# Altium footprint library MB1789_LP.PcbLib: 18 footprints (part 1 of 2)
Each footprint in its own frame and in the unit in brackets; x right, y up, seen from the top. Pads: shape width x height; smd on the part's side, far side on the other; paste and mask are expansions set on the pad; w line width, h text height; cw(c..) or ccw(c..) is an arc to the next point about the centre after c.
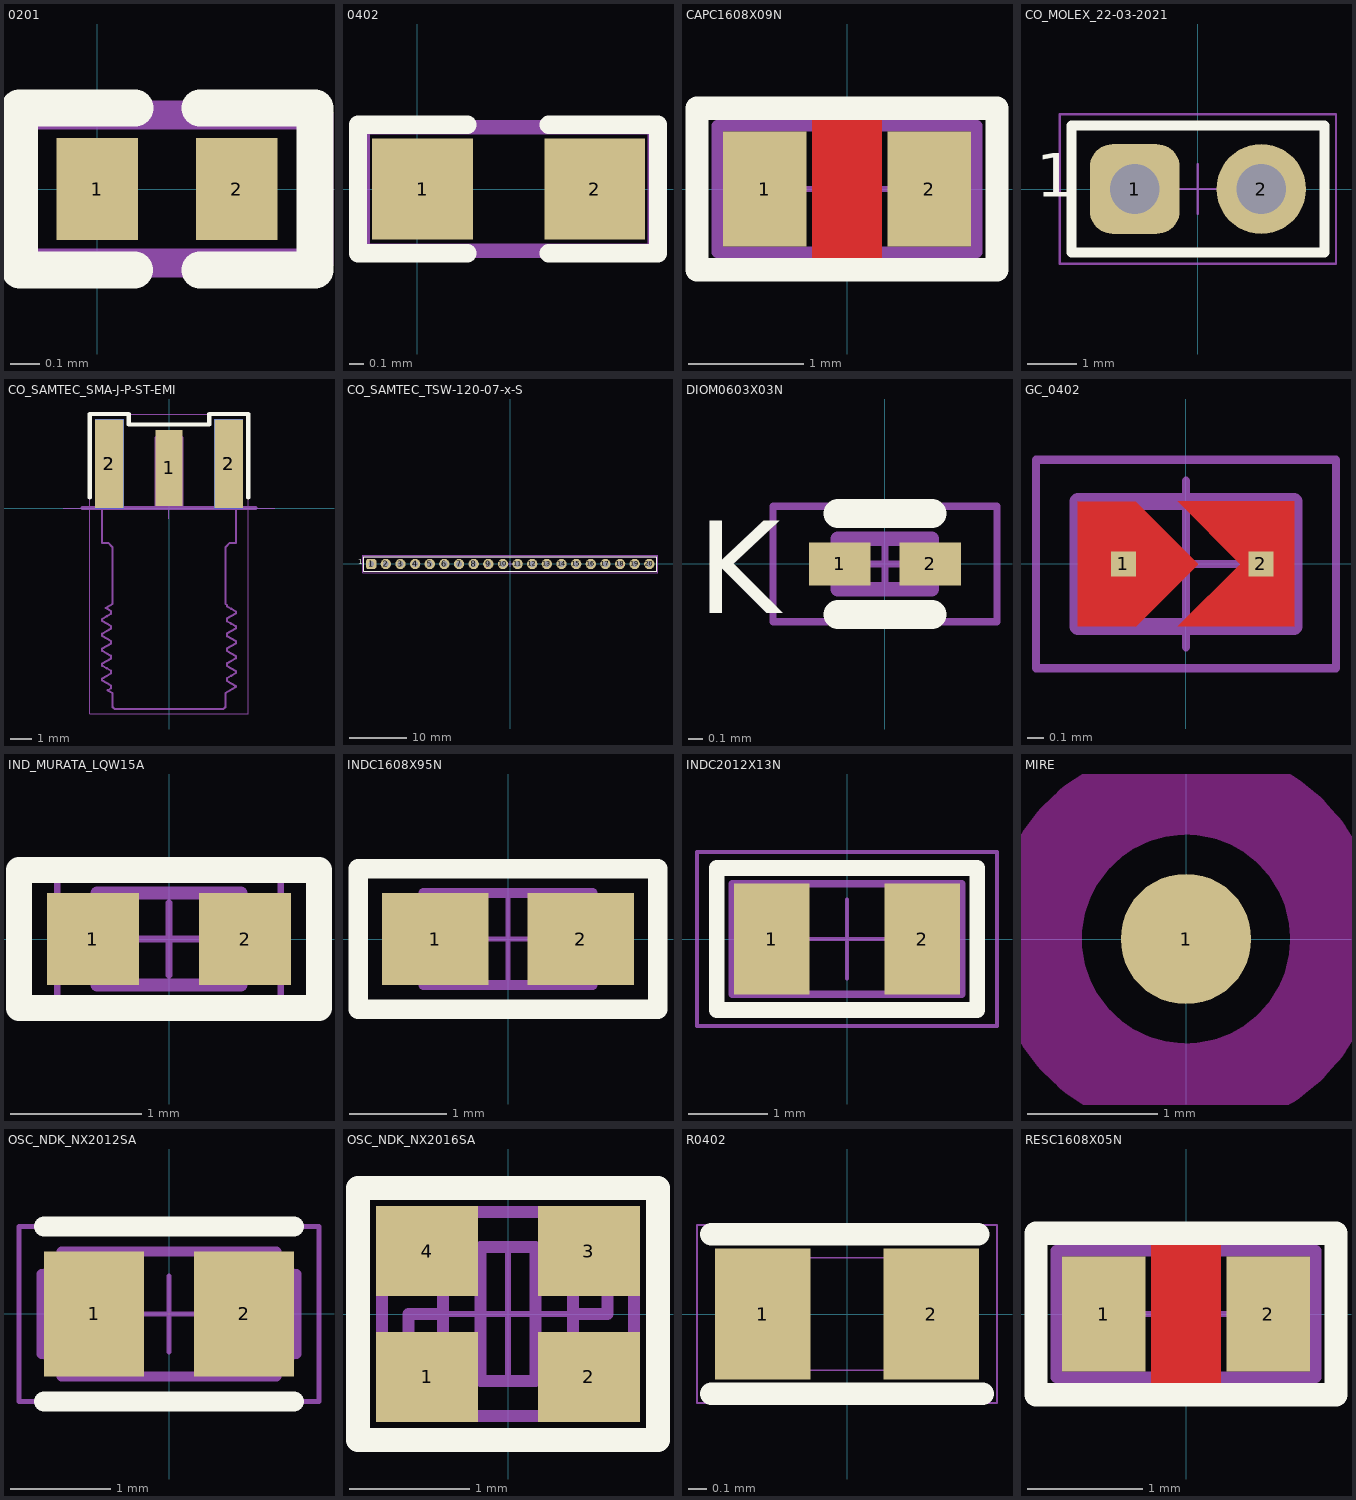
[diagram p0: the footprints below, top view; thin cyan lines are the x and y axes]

## 0201 [mm]
pads (2):
  rect 0.28x0.35 smd: 1(0,0) 2(0.48,0)
Top Overlay:
  lines w0.127: -0.268,0.279 0.13,0.279 ; -0.267,0.273 -0.267,-0.278 0.128,-0.278 ; 0.353,0.279 0.748,0.279 0.748,-0.278 0.354,-0.278
Top Assembly (Mech14):
  lines w0.1: -0.254,-0.254 0.762,-0.254 0.762,0.254 -0.254,0.254 -0.254,-0.254
  text ".Designator" at -0.44,-0.035 h1.25
3D body "User Library-Chip Cap_MLCC_0201 (0603).step": height 0.3, standoff 0, extent -0.062,-0.149 0.538,0.151

## 0402 [mm]
pads (2):
  rect 0.7x0.7 smd: 1(0.035,0) 2(1.233,0)
Top Overlay:
  lines w0.127: -0.414,-0.447 -0.414,0.447 ; -0.384,-0.447 0.348,-0.447 ; -0.384,0.447 0.348,0.447 ; 0.913,-0.447 1.674,-0.447 ; 0.913,0.447 1.674,0.447 ; 1.674,-0.444 1.674,0.444
Top Assembly (Mech14):
  lines w0.1: -0.381,-0.43 -0.381,0.431 1.651,0.431 1.651,-0.43 -0.381,-0.43
  text ".Designator" at -0.508,0.381 h1.25
3D body: height 0.82, standoff 0, extent -0.38,-0.356 0.027,0.356
3D body: height 0.82, standoff 0, extent 1.246,-0.356 1.652,0.356
3D body: height 0.77, standoff 0, extent 0.027,-0.305 1.246,0.33

## CAPC1608X09N [mm] "Chip Capacitor, 2-Leads, Body 1.60x0.80x0.90mm (0603)"
height 0.9
pads (2):
  rect 0.725x1 smd: 1(-0.713,0) 2(0.713,0)
Top Layer:
  pour cut-out: -0.3,0.7 0.3,0.7 0.3,-0.7 -0.3,-0.7
Top Overlay:
  lines w0.2: -1.3,-0.7 -1.3,0.7 1.3,0.7 1.3,-0.7 -1.3,-0.7
Top Assembly (Mech14):
  lines w0.1: -1.125,-0.55 1.125,-0.55 1.125,0.55 -1.125,0.55 -1.125,-0.55
  text ".Designator" at 0.65,0.4 h1.25
Mechanical 17:
  lines w0.05: -0.5,0 0.5,0 ; 0,-0.5 0,0.5 ; -1.3,-0.7 1.3,-0.7 1.3,0.7 -1.3,0.7 -1.3,-0.7
3D body "CAPC1608X09.step": height 0.9, standoff 0, extent -0.8,-0.4 0.8,0.4

## CO_MOLEX_22-03-2021 [mm]
height 10.8
pads (2):
  rrect50% 1.8x1.8 hole 1: 1(-1.27,0)
  round 1.8 hole 1: 2(1.27,0)
Top Overlay:
  lines w0.2: -2.54,-1.27 -2.54,1.27 2.54,1.27 2.54,-1.27 -2.54,-1.27
  text "1" at -3.25,-0.45 h1.5
Top Assembly (Mech14):
  lines w0.1: -2.54,-1.27 -2.54,1.27 2.54,1.27 2.54,-1.27 -2.54,-1.27
  text ".Designator" at 0.4,-0.55 h1.25
  text "1" at -1.6,-1.85 h1.25
Mechanical 17:
  lines w0.05: -0.5,0 0.5,0 ; 0,-0.5 0,0.5 ; -2.77,-1.5 2.77,-1.5 2.77,1.5 -2.77,1.5 -2.77,-1.5
3D body "022032021.stp": height 10.79, standoff -3.43, extent -2.413,-1.181 2.413,1.181

## CO_SAMTEC_SMA-J-P-ST-EMI [mm] "SMA Jack CMS, Edge Mountt Receptacle 50Ohm, 5-Leads, Body 6.35x6.35x9.52mm, pitch 2.825mm"
height 6.35
pads (5):
  rect 1.27x3.6 smd mask+0.05: 1(0,1.9)
  rect 1.35x4.2 smd mask+0.05: 2(-2.825,2.1) 2(2.825,2.1)
  rect 1.35x4.2 smd far side mask+0.05: 2(-2.825,2.1) 2(2.825,2.1)
Top Overlay:
  lines w0.2: -3.75,0.5 -3.75,4.45 -1.9,4.45 -1.9,3.95 1.9,3.95 1.9,4.45 3.75,4.45 3.75,0.5
Mechanical 10:
  lines w0.2: -4.1,0 4.1,0
  text "Edge of PCB" at -2,-0.825 h0.8
Top Assembly (Mech14):
  lines w0.1: -3.164,-8.074 -3.164,-8.162 -3.15,-8.169 ; -3.164,-7.369 -3.164,-7.456 -3.15,-7.464 ; -3.164,-6.663 -3.164,-6.751 -3.15,-6.758 ; -3.164,-5.958 -3.164,-6.045 -3.151,-6.052 ; -3.164,-5.252 -3.164,-5.34 -3.152,-5.346 ; -3.158,-6.052 -2.948,-6.173 -2.744,-6.291 ; -3.159,-5.951 -2.949,-5.829 -2.739,-5.708 ; -3.159,-5.346 -2.949,-5.468 -2.744,-5.586 ; -3.158,-5.245 -2.948,-5.124 -2.738,-5.002 ; -3.157,-8.169 -2.947,-8.291 -2.744,-8.408 ; -3.157,-8.067 -2.947,-7.945 -2.737,-7.823 ; -3.157,-7.464 -2.947,-7.585 -2.744,-7.703 ; -3.157,-7.361 -2.947,-7.24 -2.737,-7.118 ; -3.157,-6.758 -2.947,-6.88 -2.744,-6.997 ; -3.157,-6.656 -2.947,-6.534 -2.737,-6.413 ; -2.992,-4.737 -2.947,-4.763 -2.744,-4.88 ; -2.991,-4.732 -2.675,-4.55 -2.675,-1.85 -2.875,-1.65 -3.175,-1.65 -3.175,0 -3.175,3.81 -2.365,3.81 -2.365,0 -0.635,0 -0.635,3.335 -0.335,3.635 0,3.635 0.335,3.635 0.635,3.335 0.635,0 2.365,0 2.365,3.81 3.175,3.81 3.175,0 3.175,-1.65 2.875,-1.65 2.675,-1.85 2.675,-4.55 2.744,-4.59 2.744,-4.653 2.947,-4.77 3.157,-4.892 ; -2.9,-8.63 -2.675,-8.76 -2.675,-9.42 -2.575,-9.52 0,-9.52 2.575,-9.52 2.675,-9.42 2.675,-8.76 3.164,-8.478 3.164,-8.427 3.152,-8.42 ; -2.901,-8.624 -2.737,-8.529 ; -2.744,-8.533 -2.744,-8.404 ; -2.744,-7.828 -2.744,-7.698 ; -2.744,-7.122 -2.744,-6.993 ; -2.744,-6.417 -2.744,-6.287 ; -2.744,-5.711 -2.744,-5.582 ; -2.744,-5.006 -2.744,-4.876 ; 2.737,-7.354 2.947,-7.232 3.157,-7.111 ; 2.737,-6.649 2.947,-6.527 3.157,-6.406 ; 2.737,-5.943 2.947,-5.822 3.157,-5.7 ; 2.737,-5.237 2.947,-5.116 3.157,-4.994 ; 2.739,-8.059 2.949,-7.937 3.159,-7.816 ; 2.744,-8.185 2.744,-8.055 ; 2.744,-8.181 2.949,-8.299 3.159,-8.42 ; 2.744,-7.479 2.744,-7.35 ; 2.744,-7.475 2.948,-7.593 3.158,-7.715 ; 2.744,-6.774 2.744,-6.644 ; 2.744,-6.77 2.947,-6.887 3.157,-7.008 ; 2.744,-6.068 2.744,-5.939 ; 2.744,-6.064 2.947,-6.181 3.157,-6.303 ; 2.744,-5.363 2.744,-5.233 ; 2.744,-5.358 2.947,-5.476 3.157,-5.597 ; 3.15,-7.008 3.164,-7.016 3.164,-7.104 ; 3.15,-6.303 3.164,-6.31 3.164,-6.398 ; 3.15,-5.597 3.164,-5.605 3.164,-5.692 ; 3.151,-7.715 3.164,-7.721 3.164,-7.809 ; 3.151,-4.892 3.164,-4.899 3.164,-4.987
  text ".Designator" at 4.25,2.8 h1.25
Mechanical 16:
  lines w0.01: -5,0 5,0
Mechanical 17:
  lines w0.05: -0.5,0 0.5,0 ; 0,-0.5 0,0.5 ; 3.73,4.43 -3.75,4.43 -3.75,-9.75 3.75,-9.75 3.75,4.43
3D body "SAMTEC_SMA-J-P-H-ST-EM1.stp": height 3.8, standoff -2.55, extent -3.175,-10.133 3.175,3.197

## CO_SAMTEC_TSW-120-07-x-S [mm] "Header, 20-Leads, 50.80x2.54x10.80mm, Pitch 2.54mm"
height 10.8
pads (20):
  rrect50% 1.8x1.8 hole 1: 1(-24.13,0)
  round 1.8 hole 1: 2(-21.59,0) 3(-19.05,0) 4(-16.51,0) 5(-13.97,0) 6(-11.43,0) 7(-8.89,0) 8(-6.35,0) 9(-3.81,0) 10(-1.27,0) 11(1.27,0) 12(3.81,0) 13(6.35,0) 14(8.89,0) 15(11.43,0) 16(13.97,0) 17(16.51,0) 18(19.05,0) 19(21.59,0) 20(24.13,0)
Top Overlay:
  lines w0.2: -25.4,-1.27 -25.4,1.27 25.4,1.27 25.4,-1.27 -25.4,-1.27
  text "1" at -26.416,-0.381 h1.5
Top Assembly (Mech14):
  lines w0.1: -25.4,-1.27 -25.4,1.27 25.4,1.27 25.4,-1.27 -25.4,-1.27
  text ".Designator" at -0.1,-0.45 h1.5
  text "1" at -26.416,-0.381 h1.5
Mechanical 17:
  lines w0.05: -0.5,0 0.5,0 ; 0,-0.5 0,0.5 ; -25.63,-1.52 25.63,-1.52 25.63,1.52 -25.63,1.52 -25.63,-1.52
3D body "SAMTEC_TSW-120-07-G-S.stp": height 8.38, standoff -2.54, extent -25.464,-1.27 25.463,1.27

## DIOM0603X03N [mm] "Molded Diode, 2-Leads, Body 0.60x0.30mm"
height 0.33
pads (2):
  rect 0.425x0.3 smd: 1(-0.312,0) 2(0.313,0)
Top Overlay:
  lines w0.2: -0.325,-0.35 0.325,-0.35 ; -0.325,0.35 0.325,0.35
  text "K" at -1.3,-0.55 h1.1
Top Assembly (Mech14):
  rectangle: -0.325,-0.175 -0.125,0.175
  lines w0.1: -0.325,-0.175 0.325,-0.175 0.325,0.175 -0.325,0.175 -0.325,-0.175
  text "K" at -1.1,-0.45 h1.25
  text ".Designator" at -0.65,0.4 h1.25
Mechanical 17:
  lines w0.05: -0.175,0 0.175,0 ; 0,-0.175 0,0.175 ; -0.775,-0.4 0.775,-0.4 0.775,0.4 -0.775,0.4 -0.775,-0.4
3D body: height 0.33, standoff 0.33, extent -0.3,-0.175 -0.075,0.175
3D body: height 0.33, standoff 0, extent -0.325,-0.175 0.325,0.175

## GC_0402 [mm] "Grain de café format 0402"
height 0.035
pads (2):
  rect 0.15x0.15 smd paste-1: 1(-0.375,0) 2(0.45,0)
Top Layer:
  region: -0.05,0.375 0.65,0.375 0.65,-0.375 -0.05,-0.375 0.325,0
  region: -0.65,0.375 -0.3,0.375 0.075,0 -0.3,-0.375 -0.65,-0.375
Top Solder:
  rectangle: -0.375,-0.475 0,0.475
  rectangle: -0.65,-0.4 0.65,0.4
Top Assembly (Mech14):
  lines w0.1: -0.65,-0.375 -0.65,0.375 0.65,0.375 0.65,-0.375 -0.65,-0.375
  text ".Designator" at -0.9,0.45 h1.25
Mechanical 17:
  lines w0.05: -0.5,0 0.5,0 ; 0,-0.5 0,0.5 ; -0.9,-0.625 -0.9,0.625 0.9,0.625 0.9,-0.625 -0.9,-0.625
3D body: height 0.2, standoff -0.3, extent -0.25,-0.249 0.35,0.249
3D body: height 0.2, standoff -0.3, extent 0.1,-0.246 0.6,0.246
3D body: height 0.2, standoff -0.3, extent -0.5,-0.246 0,0.246

## IND_MURATA_LQW15A [mm] "Inductor 2-Leads,Body 1.10x0.70x0.60mm(max)"
height 0.6
pads (2):
  rect 0.7x0.7 smd: 1(-0.58,0) 2(0.58,0)
Top Overlay:
  lines w0.2: -1.143,-0.525 -1.143,0.525 1.143,0.525 1.143,-0.525 -1.143,-0.525
Top Assembly (Mech14):
  lines w0.1: -0.55,-0.35 0.55,-0.35 0.55,0.35 -0.55,0.35 -0.55,-0.35
  text ".Designator" at 1.05,-0.45 h1.25
Mechanical 17:
  lines w0.05: -0.275,0 0.275,0 ; 0,-0.275 0,0.275 ; -0.85,-0.575 -0.85,0.575 0.85,0.575 0.85,-0.575 -0.85,-0.575
3D body "IND_MURATA_LQW15AN.step": height 0.51, standoff 0, extent -0.5,-0.3 0.5,0.3

## INDC1608X95N [mm] "Chip Inductor, 2-Leads, Body 1.75x0.95x0.95mm (0603)"
height 0.95
pads (2):
  rect 1.1x0.95 smd: 1(-0.75,0) 2(0.75,0)
Top Overlay:
  lines w0.2: -1.548,-0.725 -1.548,0.725 1.548,0.725 1.548,-0.725 -1.548,-0.725
Top Assembly (Mech14):
  lines w0.1: -0.875,-0.475 -0.875,0.475 0.875,0.475 0.875,-0.475 -0.875,-0.475
  text ".Designator" at 0.45,-0.8 h1.25
Mechanical 17:
  lines w0.05: -0.475,0 0.475,0 ; 0,-0.475 0,0.475 ; -1.55,-0.725 -1.55,0.725 1.55,0.725 1.55,-0.725 -1.55,-0.725
3D body "Chip Inductor 0603.step": height 0.8, standoff 0, extent -0.8,-0.475 0.8,0.475

## INDC2012X13N [mm] "Chip Inductor, 2-Leads, Body 2.0x1.2x1.3 (0805)"
height 1.3
pads (2):
  rect 0.96x1.4 smd: 1(-0.953,0) 2(0.953,0)
Top Overlay:
  lines w0.2: -1.65,-0.9 -1.65,0.9 1.65,0.9 1.65,-0.9 -1.65,-0.9
Top Assembly (Mech14):
  lines w0.1: -1.452,-0.7 1.452,-0.7 1.452,0.7 -1.452,0.7 -1.452,-0.7
  text ".Designator" at -0.45,-0.35 h1.25
Mechanical 17:
  lines w0.05: -0.5,0 0.5,0 ; 0,-0.5 0,0.5 ; -1.9,-1.1 1.9,-1.1 1.9,1.1 -1.9,1.1 -1.9,-1.1
3D body "Chip InductorINDC2012X130N.step": height 1.18, standoff -0.02, extent -1,-0.65 1,0.65

## MIRE [mm] "Fiducial Target Round , Pad 1.0mm, Keepout 3mm"
height 0.035
pads (1):
  round 1 smd: 1(0,0)
Top Layer keep-out:
  circle w0.7: c0,0 r1.15
3D body: height 0.04, standoff 0, extent -0.499,-0.499 0.499,0.499

## OSC_NDK_NX2012SA [mm] "Crystal, 2-Leads, Body 2.05x1.20x0.55mm (Tol:-/+0.05)"
height 0.55
pads (2):
  rect 1x1.25 smd: 1(-0.75,0) 2(0.75,0)
Top Overlay:
  lines w0.2: -1.25,-0.875 1.25,-0.875 ; -1.25,0.875 1.25,0.875
Top Assembly (Mech14):
  lines w0.1: -1.275,-0.4 cw(c-1.275,-0.6) -1.077,-0.625 1.077,-0.625 cw(c1.275,-0.6) 1.275,-0.4 1.275,0.4 cw(c1.275,0.6) 1.077,0.625 -1.077,0.625 cw(c-1.275,0.6) -1.275,0.4 -1.275,-0.4
  text ".Designator" at -0.65,-0.4 h1.25
Mechanical 17:
  lines w0.05: -0.381,0 0.381,0 ; 0,-0.381 0,0.381 ; -1.5,-0.875 1.5,-0.875 1.5,0.875 -1.5,0.875 -1.5,-0.875
3D body: height 0.55, standoff 0, extent -1.038,-0.625 1.025,0.625

## OSC_NDK_NX2016SA [mm] "Crystal, 4-Leads, Body 2.10x1.61x0.50mm (max), Pitch 1.35x1.05mm"
height 0.45
pads (4):
  rect 0.85x0.75 smd: 1(-0.675,-0.525) 2(0.675,-0.525) 3(0.675,0.525) 4(-0.675,0.525)
Top Overlay:
  lines w0.2: -1.25,-1.05 1.25,-1.05 1.25,1.05 -1.25,1.05 -1.25,-1.05
  text "." at -1.475,-1.675 h4
Top Assembly (Mech14):
  lines w0.1: -0.83,-0.45 -0.83,0 -0.54,0 ; -0.54,-0.3 -0.54,0.3 ; 0.54,-0.3 0.54,0.3 ; 0.54,0 0.83,0 0.83,0.45 ; -1.05,-0.65 cw(c-1.05,-0.85) -0.85,-0.85 0.85,-0.85 cw(c1.05,-0.85) 1.05,-0.65 1.05,0.65 cw(c1.05,0.85) 0.85,0.85 -0.85,0.85 cw(c-1.05,0.85) -1.05,0.65 -1.05,-0.65 ; -0.23,-0.56 -0.23,0.56 0.23,0.56 0.23,-0.56 -0.23,-0.56
  text "." at -0.7,-0.7 h3
  text ".Designator" at 0.5,-1.15 h1.25
Mechanical 17:
  lines w0.05: -0.5,0 0.5,0 ; 0,-0.5 0,0.5 ; -1.25,-1.05 1.25,-1.05 1.25,1.05 -1.25,1.05 -1.25,-1.05
3D body "OSC_NDK_NX2016SA.STEP": height 0.5, standoff 0, extent -1,-0.8 1,0.8

## R0402 [mm]
height 0.4
pads (2):
  rect 0.51x0.7 smd mask+0.05: 1(-0.45,0) 2(0.45,0)
Top Overlay:
  lines w0.12: -0.725,-0.425 0.725,-0.425 ; -0.725,0.425 0.7,0.425
Top Assembly (Mech14):
  lines w0.01: -0.45,-0.3 -0.45,0.3 0.45,0.3 0.45,-0.3 -0.45,-0.3
  text "'.Designator'" at -2,-0.5 h0.75
Mechanical 16:
  lines w0.01: -0.8,-0.475 0.8,-0.475 0.8,0.475 -0.8,0.475 -0.8,-0.475
3D body: height 0.4, standoff 0, extent -0.455,-0.305 0.455,0.305
3D body "R0402.STEP": height 0.34, standoff 0, extent -0.52,-0.3 0.52,0.3

## RESC1608X05N [mm] "Chip Resistor, 2-Leads, Body 1.60x0.80mm (0603)"
height 0.5
pads (2):
  rect 0.725x1 smd: 1(-0.713,0) 2(0.713,0)
Top Layer:
  pour cut-out: -0.3,0.7 0.3,0.7 0.3,-0.7 -0.3,-0.7
Top Overlay:
  lines w0.2: -1.3,-0.7 -1.3,0.7 1.3,0.7 1.3,-0.7 -1.3,-0.7
Top Assembly (Mech14):
  lines w0.1: -1.125,-0.55 1.125,-0.55 1.125,0.55 -1.125,0.55 -1.125,-0.55
  text ".Designator" at 0.65,0.4 h1.25
Mechanical 17:
  lines w0.05: -0.5,0 0.5,0 ; 0,-0.5 0,0.5 ; -1.3,-0.7 1.3,-0.7 1.3,0.7 -1.3,0.7 -1.3,-0.7
3D body "RESC1608X05N.step": height 0.45, standoff 0, extent -0.775,-0.425 0.775,0.425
